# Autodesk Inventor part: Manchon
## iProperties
Shininess: 64.0
Length Units: 11269
Angle Units: 11279
Time Units: 11290
Mass Units: 11283
Length Display Precision: 3
Angle Display Precision: 2
Compacted: True
Part Number: Manchon
Document SubType Name: Modeling
Created: 2005-01
Material: Par défaut
Designer: lolo (Laurent Moretti)
Density: 0.0
Volumn: 0.0
Area: 0.0
PropertySet Name: Model Information
Control State: 0
Master: False
Checked Out: False
Author: lolo (Laurent Moretti)
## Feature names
1. Révolution1 [Revolution]
2. Congé1 [Fillet]
3. Congé2 [Fillet]
4. Congé3 [Fillet]
